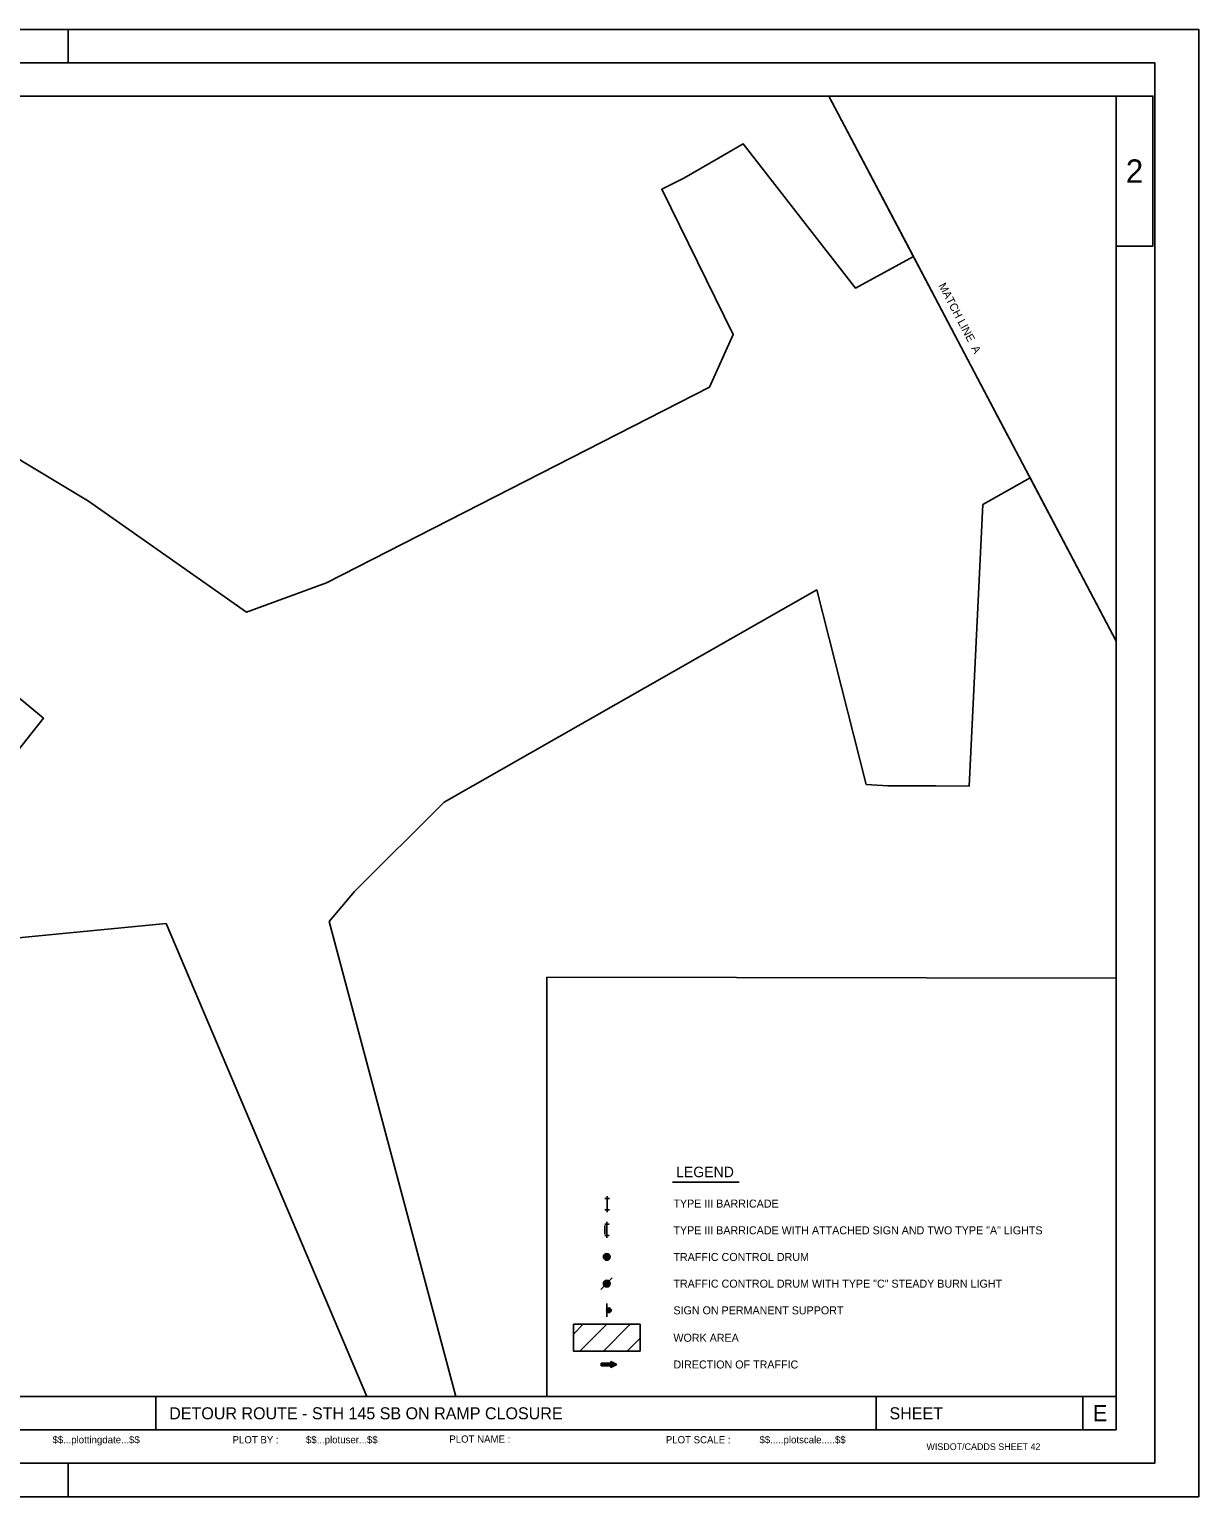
# Model space of a CAD drawing. Extents: x 358553 to 360253, y 132337 to 133437.
# Drawn here: x 359376 to 360253, y 132337 to 133437 of the extents above; entities that cross this region are included whole.
import ezdxf

# ---------------------------------------------------------------- set-up
doc = ezdxf.new("R2010")
doc.units = 0
for name, color, linetype in [('Default', 7, 'Continuous'), ('P_ALI_100_PIData', 7, 'Continuous'), ('P_ALI_200_PIData', 7, 'Continuous'), ('P_ALI_200_Sta', 7, 'Continuous'), ('P_ALI_200_Tic', 7, 'Continuous'), ('P_ALI_20_PIData', 7, 'Continuous'), ('P_ALI_20_Sta', 7, 'Continuous'), ('P_ALI_50_Equation', 7, 'Continuous'), ('P_ALI_50_PIData', 7, 'Continuous'), ('P_ALI_50_Sta', 7, 'Continuous')]:
    doc.layers.add(name, color=color, linetype=linetype)

msp = doc.modelspace()

# ---------------------------------------------------------------- linework, layer by layer
at = {"layer": 'Default'}
msp.add_lwpolyline([(360190.8, 132411.9), (358615.8, 132411.9), (358615.8, 133386.9), (359975.4, 133386.9), (360190.8, 132978.3)], close=True, dxfattribs=at)
for points in [[(358615.8, 133386.9), (359975.4, 133386.9), (360038.9, 133266.5), (359995.4, 133242.8), (359911.1, 133351), (359892.5, 133340.4), (359866.5, 133325.4), (359850.1, 133317), (359903.7, 133208.1), (359885.9, 133168.6), (359598.6, 133021.9), (359538.8, 132999.9), (359420.2, 133083.1), (359239.6, 133191.8)], [(358987.8, 133251.2), (359386.6, 132920.5), (359304.4, 132816.8)], [(359349.3, 132754.2), (359478.5, 132766.7), (359628.9, 132411.9), (359695.7, 132411.9), (359600.6, 132768.2), (359619.8, 132790.6), (359687, 132857.6), (359966.3, 133016.7), (360003.4, 132870.9), (360019.5, 132869.9), (360055.5, 132869.9), (360080.6, 132869.6), (360090.7, 133080.6), (360126.3, 133100.8), (360190.8, 132978.3), (360190.8, 132725.7), (359764, 132726.3), (359764, 132411.9), (358615.8, 132411.9)]]:
    msp.add_lwpolyline(points, dxfattribs=at)
at = {"layer": 'P_ALI_100_PIData'}
for p, q in [((359809.2, 132560.5), (359809.2, 132562.2)), ((359809.2, 132560.5), (359807.5, 132560.5)), ((359809.2, 132552), (359807.5, 132552)), ((359809.2, 132552), (359809.2, 132560.5)), ((359809.2, 132560.5), (359810.9, 132560.5)), ((359810.9, 132552), (359809.2, 132552)), ((359809.2, 132552), (359809.2, 132550.3)), ((359809, 132541.2), (359807.3, 132541.2)), ((359807.3, 132533.7), (359807.3, 132540.2)), ((359809, 132541.2), (359809, 132542.9)), ((359809, 132532.7), (359809, 132541.2)), ((359809, 132541.2), (359810.7, 132541.2)), ((359809, 132532.7), (359807.3, 132532.7)), ((359810.7, 132532.7), (359809, 132532.7)), ((359809, 132532.7), (359809, 132531)), ((359804.5, 132492.3), (359813, 132500.9)), ((359808.8, 132471.6), (359808.8, 132481.6)), ((359783.8, 132458.8), (359791.1, 132466.1)), ((359788.7, 132446), (359808.8, 132466.1)), ((359806.4, 132446), (359826.4, 132466.1)), ((359824.1, 132446), (359833.8, 132455.7))]:
    msp.add_line(p, q, dxfattribs=at)
msp.add_lwpolyline([(359783.8, 132466.1), (359833.8, 132466.1), (359833.8, 132446), (359783.8, 132446)], close=True, dxfattribs=at)
for centre, radius in [((359808.8, 132516.6), 2.5), ((359808.8, 132516.6), 2), ((359808.8, 132516.6), 1.5), ((359808.8, 132516.6), 1), ((359808.8, 132516.6), 0.5), ((359808.8, 132516.6), 0.25), ((359808.8, 132496.6), 2.5), ((359808.8, 132496.6), 2), ((359808.8, 132496.6), 1.5), ((359808.8, 132496.6), 1), ((359808.8, 132496.6), 0.5), ((359808.8, 132496.6), 0.25), ((359810.5, 132476.6), 1.75), ((359810.5, 132476.6), 1), ((359810.5, 132476.6), 0.25)]:
    msp.add_circle(centre, radius, dxfattribs=at)
at = {"layer": 'P_ALI_200_PIData'}
for points in [[(358552.6, 132336.9), (360252.6, 132336.9), (360252.6, 133436.9), (358552.6, 133436.9)], [(358564.6, 132361.9), (360219.6, 132361.9), (360219.6, 133411.9), (358564.6, 133411.9)]]:
    msp.add_lwpolyline(points, close=True, dxfattribs=at)
at = {"layer": 'P_ALI_200_Sta'}
for p, q in [((359380.1, 133436.9), (359430.1, 133436.9)), ((359405.1, 133436.9), (359405.1, 133411.9)), ((360202.6, 133436.9), (360252.6, 133436.9)), ((360252.6, 133386.9), (360252.6, 133436.9)), ((358615.8, 133386.9), (360190.8, 133386.9)), ((360190.8, 132386.9), (360190.8, 133386.9)), ((358615.8, 132411.9), (360190.8, 132411.9)), ((359470.8, 132386.9), (359470.8, 132411.9)), ((360010.8, 132386.9), (360010.8, 132411.9)), ((360165.8, 132386.9), (360165.8, 132411.9)), ((358615.8, 132386.9), (360190.8, 132386.9)), ((360252.6, 132336.9), (360252.6, 132386.9)), ((359405.1, 132336.9), (359405.1, 132361.9)), ((359380.1, 132336.9), (359430.1, 132336.9)), ((360202.6, 132336.9), (360252.6, 132336.9))]:
    msp.add_line(p, q, dxfattribs=at)
msp.add_lwpolyline([(360190.8, 133386.9), (360218.3, 133386.9), (360218.3, 133274.4), (360190.8, 133274.4)], close=True, dxfattribs=at)
at = {"layer": 'P_ALI_200_Tic'}
msp.add_lwpolyline([(358552.6, 133436.9), (360252.6, 133436.9), (360252.6, 132336.9), (358552.6, 132336.9), (358552.6, 133436.9)], dxfattribs=at)
at = {"layer": 'P_ALI_20_PIData'}
for p, q in [((359804.7, 132437.1), (359804.7, 132434.9)), ((359804.7, 132437.1), (359811.9, 132437.1)), ((359804.7, 132436.7), (359815, 132436.7)), ((359804.7, 132436.2), (359815.9, 132436.2)), ((359804.7, 132436), (359804.7, 132436)), ((359804.7, 132435.8), (359815.8, 132435.8)), ((359804.7, 132435.3), (359814.9, 132435.3)), ((359804.7, 132434.9), (359811.9, 132434.9)), ((359816.3, 132436), (359811.9, 132438.3)), ((359811.9, 132438.3), (359811.9, 132433.8)), ((359811.9, 132438), (359812.3, 132438)), ((359811.9, 132437.6), (359813.2, 132437.6)), ((359811.9, 132437.1), (359814.1, 132437.1)), ((359816.3, 132436), (359811.9, 132433.8)), ((359811.9, 132434.9), (359814, 132434.9)), ((359811.9, 132434.4), (359813.2, 132434.4)), ((359811.9, 132434), (359812.3, 132434))]:
    msp.add_line(p, q, dxfattribs=at)
at = {"layer": 'P_ALI_20_Sta'}
msp.add_line((359858.2, 132572.7), (359908.2, 132572.7), dxfattribs=at)
at = {"layer": 'P_ALI_50_Equation'}
msp.add_lwpolyline([(358552.6, 133436.9), (360252.6, 133436.9), (360252.6, 132336.9), (358552.6, 132336.9)], close=True, dxfattribs=at)
at = {"layer": 'P_ALI_50_PIData'}
msp.add_line((360037.1, 133269.8), (360109.6, 133132.3), dxfattribs=at)

# ---------------------------------------------------------------- texts
at = {"layer": 'P_ALI_200_Sta'}
for s, height, p in [('2', 17.5, (360198, 133321.9)), ('DETOUR ROUTE - STH 145 SB ON RAMP CLOSURE', 9, (359480.8, 132394.9)), ('SHEET ', 9, (360020.8, 132394.9)), ('E', 12, (360173.4, 132393.5)), ('PLOT NAME :                      ', 5.4, (359690.8, 132377.4)), ('PLOT SCALE : ', 5.4, (359853.1, 132376.9)), ('$$.....plotscale.....$$', 5.4, (359923.3, 132376.9)), ('WISDOT/CADDS SHEET 42', 5, (360048.5, 132371.9))]:
    msp.add_text(s, height=height, dxfattribs=at).set_placement(p)
for s, p in [('$$...plottingdate...$$', (359393.3, 132376.9)), ('PLOT BY :', (359528.3, 132376.9)), ('$$...plotuser...$$', (359583.3, 132376.9))]:
    msp.add_text(s, height=5.4, rotation=360, dxfattribs=at).set_placement(p)
at = {"layer": 'P_ALI_20_Sta'}
for s, height, p in [('LEGEND', 7.88, (359860.8, 132576.4)), ('TYPE III BARRICADE', 6, (359858.8, 132553.6)), ('TYPE III BARRICADE WITH ATTACHED SIGN AND TWO TYPE "A" LIGHTS', 6, (359858.8, 132533.6)), ('TRAFFIC CONTROL DRUM', 6, (359858.8, 132513.6)), ('TRAFFIC CONTROL DRUM WITH TYPE "C" STEADY BURN LIGHT', 6, (359858.8, 132493.6)), ('SIGN ON PERMANENT SUPPORT', 6, (359858.8, 132473.6)), ('WORK AREA', 6, (359858.8, 132453)), ('DIRECTION OF TRAFFIC', 6, (359858.8, 132433))]:
    msp.add_text(s, height=height, rotation=359.9953, dxfattribs=at).set_placement(p)
at = {"layer": 'P_ALI_50_Sta'}
msp.add_text('MATCH LINE  A', height=6, rotation=297.713, dxfattribs=at).set_placement((360057.3, 133244.9))

doc.saveas('drawing.dxf')
